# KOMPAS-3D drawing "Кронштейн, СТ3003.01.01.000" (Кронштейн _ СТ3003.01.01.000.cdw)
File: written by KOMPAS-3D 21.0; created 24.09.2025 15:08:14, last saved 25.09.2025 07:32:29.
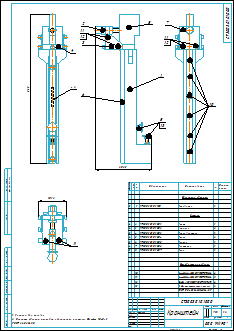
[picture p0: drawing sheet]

Sheet 1: A2, portrait

Document properties: Полное имя файла: ..\..\3D\Кронштейн _ СТ3003.01.01.000\Кронштейн _ СТ3003.01.01.000.a3d; Масса: 9.381703

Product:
- Part/product: Кронштейн  | designation СТ3003.01.01.000
    Масса: 9.381703
    Форматы листов документа: A2
  - Component [standard]: Гайка шестигранная низкая ГОСТ ISO 4035-М12-05-A2P  | qty 2  | pos. 13  | Материал: Сталь (density 1000 kg/m3); Масса: 0.001154; Раздел спецификации: Стандартные изделия; Рассекать на разрезах: no; additional columns: M12 - 05 - A2P
  - Component [detail]: Опора  | designation СТ3003.01.01.004  | qty 2  | pos. 5  | Материал: Круг$d35 ГОСТ 2590-2006;Ст3сп ГОСТ 535-2005$ (density 7850 kg/m3); Масса: 0.078797; Форматы листов документа: A4; source file: ..\..\3D\Кронштейн _ СТ3003.01.01.000\Опора _ СТ3003.01.01.004.m3d, Опора _ СТ3003.01.01.004.cdw
  - Component [standard]: Винт М6-6gx20.56.019 ГОСТ 11738-84  | qty 6  | pos. 10  | Материал: Сталь 30 ГОСТ 1050-2013 (density 1000 kg/m3); Масса: 0.00666; Раздел спецификации: Стандартные изделия; Рассекать на разрезах: no
  - Component [standard]: Винт М8-6gx25.56.019 ГОСТ 11738-84  | qty 8  | pos. 11  | Материал: Сталь 30 ГОСТ 1050-2013 (density 1000 kg/m3); Масса: 0.01513; Раздел спецификации: Стандартные изделия; Рассекать на разрезах: no
  - Component [standard]: Шайба A.8.01.10.019 ГОСТ 11371-78  | qty 6  | pos. 12  | Масса: 0.001828; Раздел спецификации: Стандартные изделия; Рассекать на разрезах: no
  - Component [detail]: Пластина  | designation СТ3003.01.01.006  | pos. 7  | Материал: Лист$dБ-ПН-НО-16 ГОСТ 19903-2015;Ст3сп ГОСТ 14637-89$ (density 7850 kg/m3); Масса: 0.669577; Форматы листов документа: A4; source file: ..\..\3D\Кронштейн _ СТ3003.01.01.000\Пластина _ СТ3003.01.01.006.m3d
  - Component [detail]: Упор  | designation СТ3003.01.01.007  | pos. 8  | Материал: Сталь 45  ГОСТ 1050-2013 (density 7810 kg/m3); Масса: 1.271359; Форматы листов документа: A3; source file: ..\..\3D\Кронштейн _ СТ3003.01.01.000\Упор _ СТ.3003.01.01.007.m3d
  - Component [detail]: Косынка  | designation СТ3003.01.01.002  | qty 2  | pos. 3  | Материал: Лист$dБ-ПН-НО-6 ГОСТ 19903-2015;Ст3сп ГОСТ 14637-89$ (density 7850 kg/m3); Масса: 0.116828; Форматы листов документа: A4; source file: ..\..\3D\Кронштейн _ СТ3003.01.01.000\Косынка _ СТ3003.01.01.002.m3d, Косынка _ СТ3003.01.01.002.cdw
  - Component [detail]: Направляющая  | designation СТ3003.01.01.003  | pos. 4  | Материал: Сталь 45  ГОСТ 1050-2013 (density 7810 kg/m3); Масса: 0.806848; Форматы листов документа: A3; source file: ..\..\3D\Кронштейн _ СТ3003.01.01.000\Направляющая _ СТ3003.01.01.003.m3d
  - Component [detail]: Планка  | designation СТ3003.01.01.005  | pos. 6  | Материал: Сталь 45  ГОСТ 1050-2013 (density 7810 kg/m3); Масса: 1.670176; Форматы листов документа: A3; source file: ..\..\3D\Кронштейн _ СТ3003.01.01.000\Планка _ СТ3003.01.01.005.m3d, Планка _ СТ3003.01.01.005.cdw
  - Component [assembly]: Основание  | designation СТ3003.01.01.100  | pos. 1  | Масса: 4.086618; Форматы листов документа: A3; source file: ..\..\3D\Кронштейн _ СТ3003.01.01.000\Основание _ СТ3003.01.01.100\Основание _ СТ3003.01.01.100.a3d, Основание _ СТ3003.01.01.100\Основание _ СТ3003.01.01.100.cdw
  - Component [detail]: Винт  | designation СТ3003.01.01.001  | pos. 2  | Материал: Круг$d30 ГОСТ 2590-2006;Ст3сп ГОСТ 535-2005$ (density 7850 kg/m3); Масса: 0.311599; Форматы листов документа: A4; additional columns: 110; source file: ..\..\3D\Кронштейн _ СТ3003.01.01.000\Винт _ СТ3003.01.01.001.m3d, Винт _ СТ3003.01.01.001.cdw

Title block, sheet 1: Наименование: Кронштейн; designation: СТ3003.01.01.000; Масса: 9,38; Количество листов документа: 1; organisation: ООО "МИРО"; Форматы листов документа: A2; stored path: C:\Users\1\Yandex.Disk\Документы\Новая папка\Стапель №2\Стапель _ СТ3003.00.00.000\Опора _ СТ3003.01.00.000\2D\Кронштейн _ СТ3003.01.01.000\Кронштейн _ СТ3003.01.01.000.cdw; Разработал: Тимонин

Views: Вид 1, Спереди
Referenced files in C:\Users\1\Yandex.Disk\Документы\Новая папка\Стапель №2\Стапель _ СТ3003.00.00.000\Опора _ СТ3003.01.00.000\3D\Кронштейн _ СТ3003.01.01.000\: Кронштейн _ СТ3003.01.01.000.a3d, Косынка _ СТ3003.01.01.002.m3d, Планка _ СТ3003.01.01.005.m3d, Опора _ СТ3003.01.01.004.m3d, Направляющая _ СТ3003.01.01.003.m3d, Винт _ СТ3003.01.01.001.m3d, Пластина _ СТ3003.01.01.006.m3d, Упор _ СТ.3003.01.01.007.m3d
Referenced files in C:\Users\1\Yandex.Disk\Документы\Новая папка\Стапель №2\Стапель _ СТ3003.00.00.000\Опора _ СТ3003.01.00.000\2D\Кронштейн _ СТ3003.01.01.000\: Косынка _ СТ3003.01.01.002.cdw, Планка _ СТ3003.01.01.005.cdw, Опора _ СТ3003.01.01.004.cdw, Винт _ СТ3003.01.01.001.cdw
Referenced files in C:\Users\1\Yandex.Disk\Документы\Новая папка\Стапель №2\Стапель _ СТ3003.00.00.000\Опора _ СТ3003.01.00.000\3D\Кронштейн _ СТ3003.01.01.000\Основание _ СТ3003.01.01.100\: Основание _ СТ3003.01.01.100.a3d, Пластина _ СТ3003.01.01.101.m3d, Пластина _ СТ3003.01.01.102.m3d
Referenced files in C:\Users\1\Yandex.Disk\Документы\Новая папка\Стапель №2\Стапель _ СТ3003.00.00.000\Опора _ СТ3003.01.00.000\2D\Кронштейн _ СТ3003.01.01.000\Основание _ СТ3003.01.01.100\: Основание _ СТ3003.01.01.100.cdw
Referenced files in C:\Program Files\ASCON\KOMPAS-3D v21\Libs\PartLib\DATA\VAULT\Methods\Kompas\3D\: PLib_Screw_GOST_11738_1500.m3d, PLib_Washer_1_712.m3d
Referenced files in C:\Program Files\ASCON\KOMPAS-3D v21\Libs\PARTLib\DATA\vault\Methods\Kompas\3D\: PLib_Nut_ISO_1100.m3d
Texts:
  Винт М6-6gx20.56.019 ГОСТ 11738-84
  Крепежное изделие ГОСТ
  Винт
  ГОСТ
  Гайка шестигранная низкая ГОСТ ISO 4035-М12-05-A2P
  Гайка шестигранная низкая
  ГОСТ ISO
  СТ3003.01.01.002
  Косынка
  Винт М8-6gx25.56.019 ГОСТ 11738-84
  СТ3003.01.01.005
  Планка
  СТ3003.01.01.004
  Опора
  Шайба A.8.01.10.019 ГОСТ 11371-78
  Шайба
  СТ3003.01.01.003
  Направляющая
  СТ3003.01.01.001
  СТ3003.01.01.006
  Пластина
  СТ3003.01.01.007
  Упор
  СТ3003.01.01.100
  Основание
  ГОСТ ISO 4035-М12-05-A2P
  СТ3003.01.00.000
  СТ3003.01.01.101
  СТ3003.01.01.101 Пластина
  СТ3003.01.01.102
  СТ3003.01.01.102 Пластина
  СТ3003.01.01.100 Основание
  СТ3003.01.01.005 Планка
  СТ3003.01.01.003 Направляющая
  СТ3003.01.01.006 Пластина
  СТ3003.01.01.002 Косынка
  СТ3003.01.01.007 Упор
  СТ3003.01.01.001 Винт
  СТ3003.01.01.004 Опора
  СТ3003.01.01.000 Кронштейн
Dimensions and other numbers on the sheet: 535; 4; 56; 40Х; 019; 1; 05; 01; 10; 6; 13; 2; 3; 11; 8; 5; 12; 7; 1:2; 9,38

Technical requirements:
  Размеры для справок.
  Нанести ударным способом обозначение чертежа. Шрифт 10-Пр3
